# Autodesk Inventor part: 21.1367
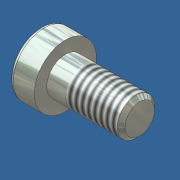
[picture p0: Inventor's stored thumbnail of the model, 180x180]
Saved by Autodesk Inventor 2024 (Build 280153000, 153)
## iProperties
Created: 2006-02
Part Number: 21.1367
Material: Steel, Mild
Description: M6X14 SHCS
Document SubType Name: Modeling
Standard: DIN 7984
Designer: Andy Moles
Standards Organization: DIN
Language: en-US
Size Designation: M6 x 12
Categories: <MemberInstance><Categories><Category DisplayName="Fasteners" InternalName="e4da775c-781d-43d5-af7c-5136215cf5a6" Mnemonic="FSTN"><Category DisplayName="Bolts"
Density: 7.85 g/cm^3
Mass: 5.14584 g
Surface Area: 5.76463 cm^2
Volume: 0.655521 cm^3
Appearance: Zinc
Author: Andy Moles
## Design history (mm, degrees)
body "Solid1"
workplane "Work Plane1"
revolve "Body" stored, may be unused: angle "d10" = 90 deg
sketch "Sketch2"
  geometry: L1 (0, -6)-(0, 8) reference; L2 (-6, 0)-(8, 0) reference; L3 (2.309, 0)-(1.155, -2); L4 (1.155, -2)-(-1.155, -2); L5 (-1.155, -2)-(-2.309, 0); L6 (-2.309, 0)-(-1.155, 2); L7 (-1.155, 2)-(1.155, 2); L8 (1.155, 2)-(2.309, 0); 2 further points
  constraints: 12 end point, 1 coincident, 1 horizontal alignment, 1 point on line, 12 other
extrude "Slot" join sketch "Sketch2" stored distance "d11" = 10; taper "d12" = 0 deg
fillet "Fillet1" dims "d17" = 0.6 (= RR)
feature "Thread" dims "d13" = 14, "d14" = 0
chamfer "Chamfer1" distance "d15" = 0.61345 (= -0.5 x SPD + 0.5 x GD); stored, may be unused: second distance "d16" = 0.61345 (= GUL), angle "d27" = 45 deg
sketch "Sketch1"
  geometry: L1 (0.333, 0)-(14, 0); L2 (14, 0)-(14, 3); L3 (14, 3)-(1, 3); L4 (1, 3)-(0.386, 3); L5 (0.386, 3)-(0, 3); L6 (0, 3)-(0, 5); L7 (0, 5)-(-4, 5); L8 (-4, 5)-(-4, 2.309); L9 (-4, 2.309)-(-1, 2.309); L10 (-1, 2.309)-(0.333, 0); L11 (-5.8, 0)-(19.4, 0) reference; L12 (0, -0.5)-(0, 6.5) reference; L13 (1, 3)-(0, 3)
  constraints: 22 end point, 6 parallel, 2 collinear, 2 perpendicular, 1 horizontal, 1 midpoint
  dimensions: "d1" = 13 distance from line of L3.end L2 (= GEL); "d2" = 0.61355 distance of L4.end L3.end (computed from GAL); "d3" = 4 distance between parallel lines of L8 L6 (= KOH); "d4" = 3 distance of L8.end L9.end (= INTI); "d5" = 60 deg angle of L10 L1; "d6" = 6 diameter of L3 L1 (= GD); "d7" = 6 diameter of L5 L1 (= BDM); "d8" = 4.6188 diameter of L9 L1 (= 1.1547 x SW); "d9" = 10 diameter of L7 L1 (= KOD); "d26" = 14 distance between parallel lines of L12 L2 (= NLG)
other parameters: "GD" = 6 (= NND) [user parameter; used in 2 equation terms], "NLG" = 14 [user parameter; used in 1 equation term], "GEL" = 13 [user parameter; used in 1 equation term], "KOD" = 10 [user parameter; used in 1 equation term], "KOH" = 4 [user parameter; used in 1 equation term], "INTI" = 3 [user parameter; used in 1 equation term], "GAL" = 0.61345 (= 0.61345 x PTC) [user parameter; used in 1 equation term], "GUL" = 0.61345 (= 0.61345 x PTC) [user parameter; used in 1 equation term], "BDM" = 6 (= NND) [user parameter; used in 1 equation term], "SW" = 4 [user parameter; used in 2 equation terms], "RR" = 0.6 [user parameter; used in 1 equation term], "SPD" = 4.7731 (= NND - 1.2269 x PTC) [user parameter; used in 1 equation term], "d19" = 0, "d28" = 0, "d29" = 0, "TOA" = 30 deg [user parameter], "GD1" = 4.7731 (= THREADDIA - 1.2269 x PTC) [user parameter], "THREADDIA" = 6 [user parameter; used in 1 equation term], "FAWI" = 45 deg [user parameter], "ANG" = 120 deg [user parameter], "PTC" = 1 [user parameter; used in 5 equation terms], "NND" = 6 [user parameter; used in 3 equation terms], "E0" = 4.62 (= 1.155 x SW) [user parameter]
